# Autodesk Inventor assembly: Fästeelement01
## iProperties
Created: 2001-12
Part Number: Fästeelement01
Document SubType Name: Assembly
Designer: Tobben
Control State: 0
Master: False
Checked Out: False
Shininess: 64.0
Length Units: 11269
Angle Units: 11279
Time Units: 11290
Mass Units: 11283
Length Display Precision: 3
Angle Display Precision: 2
Density: 0.0
Volumn: 0.0
Area: 0.0
PropertySet Name: Model Information
Author: Tobben
